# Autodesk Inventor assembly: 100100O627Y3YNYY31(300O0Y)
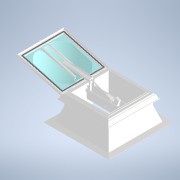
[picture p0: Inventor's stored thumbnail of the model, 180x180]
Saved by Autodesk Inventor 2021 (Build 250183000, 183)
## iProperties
Category: PARTsolutions
Company: KINGSPAN
Created: 2026-04
Part Number: 100100O627Y3YNYY31(300O0Y)
Catalog Web Link: www.3dfindit.com
Description: LK classic-
Vendor: KINGSPAN
Document SubType Name: Assembly
Designer: psAdmin
Manufacturer: KINGSPAN
Mass: 161081 g
Surface Area: 119021 cm^2
Volume: 161081 cm^3
Density: 1 g/cm^3
Title: LKclassic100100O627Y3YNYY31
Author: Cadenas PARTsolutions
PSOL_IDENT_0: {$CADENAS_DATA/23d-libs/kingspan_kla/light_dome_classic/light_dome_classic_asmtab.prj},281 {VTYP=3D}
PSOL_IDENT_1: ,{STYP=ASSTAB},{NB=100100O627Y3YNYY31(300O0Y)},{LINA=LKclassic100100O627Y3YNYY31},{NN=LK classic},{D
PSOL_IDENT_2: ATE=05.11.2025 13:48:10},{GEOMDATE=13.01.2025 13:03:38},{VERSION=},{LINEID=10},{WBVAR=LODLEVEL,L,W,T
PSOL_IDENT_3: G,TS,WF,DP,OP,OC,GCW,SD,IPM,EVADSS,SSSO,SF,BA,INS,RT},{WBNUMERIC=W,RT}  {NB=100100O627Y3YNYY31(300O0
PSOL_IDENT_4: Y)},{LINA=LKclassic100100O627Y3YNYY31},{KT=DUMMY},{IDNR=},{PN=LK classic},{LODLEVEL=300},{L=100},{W=
PSOL_IDENT_5: 100},{DRIVE=1},{WX=100,150,200,250,300},{TG=O},{TS=6},{WF=Y},{DP=2},{OP=7},{OC=O},{SM=N},{GCW=Y},{SD=
PSOL_IDENT_6: 3},{IPM=Y},{EVADSS=N},{SSSO=Y},{SF=Y},{BA=3},{INS=1},{INSX='1','i - insulation','2','ih - enhanced i
PSOL_IDENT_7: nsulation'},{BAX='3', 'AK50 PVC', '2', 'AK30 PVC' , '7'  , 'AK30 AL/ST', '8', 'AK40 AL/ST', '9'  , '
PSOL_IDENT_8: AK50 AL/ST', '13' , 'AK30 AL/AL', '14' , 'AK40 AL/AL', '15' , 'AK50 AL/AL', '16' , 'AK50 ST-TG', '10'
PSOL_IDENT_9: , 'AK30 ST', '11'  , 'AK40 ST', '12', 'AK50 ST'},{UVD=1.9},{UVDU=calculated by excell tool},{LT=13},
PSOL_IDENT_10: {GV=13},{SI=22},{WFX='Y','Yes','N','No'},{OPX='7','Electric Actuator - 24/48 v A/Z'},{TSX='1','2 -sh
PSOL_IDENT_11: elled', '2shell.png','2','3-shelled', '3shell.png','3','PC-st 16/7 + 1 shell','pc16_3.png', '4','PC-
PSOL_IDENT_12: st 16/7 + 2 shells ', 'pcst16_2shells.png', '5','2‐shelled with heat‐stop coating', '2shell.png','6'
PSOL_IDENT_13: ,'3‐shelled with heat‐stop coating', '3shell.png'},{LX=1000},{XWX=1000},{ANG=9.7947},{ROT=-15},{PPAT
PSOL_IDENT_14: H=parts/light_dome_classic_asmtpl.prj},{IBM=LKclassic100100O627Y3YNYY31},{SFX='Y','Yes','N','No'},{D
PSOL_IDENT_15: PX='3', 'Fixed','1', 'Natural ventilation','4','NSHE', '2'  , 'NSHEV'},{OCX='O', 'Open', 'C', 'Close
PSOL_IDENT_16: d'},{SMX='N', 'No'},{VERPRA=ErroR},{EVADSSX='N','No'},{RT=0},{SDX='1', 'RSM - round bar fall-through
PSOL_IDENT_17: protection mat', '2'  , 'EAD - laser cut fall-through protection mat', '3'  , 'HDS - fall through/h
PSOL_IDENT_18: ale protection and shading system'},{OCX1=C},{OPX1='7','Electric Actuator - 24/48 v A/Z'}
NB: 100100O627Y3YNYY31(300O0Y)
NN: LK classic
NBSYN: $L.$W.$TG.$TS.$DP.$OP.$GCW.$SD.$IPM.$EVADSS.$SSSO.$SF.$BA.$INS.($LODLEVEL.$OC.$RT.$WF.)
LINA: LKclassic100100O627Y3YNYY31
CATALOG: Light + Air
PN: LK classic
LODLEVEL: 300
L: 100
W: 100
TG: opal
TS: 3‐shelled with heat‐stop coating opal
DP: NSHEV
OP: NSHEV 24/48 V LK incl. ventilation function
OC: Open
GCW: Yes
SD: HDS - fall through/hale protection and shading system
IPM: Yes
EVADSS: No
SF: Yes
BA: AK PVC 50
INS: i - insulation
UVD: 1.9
LT: 13
GV: 13
SI: 22
RT: 0
SUPPLIER: KINGSPAN
ARTICLENO: 100100O627Y3YNYY31(300O0Y)
BOMINFO: LKclassic100100O627Y3YNYY31
CREATOR: CADENAS GmbH
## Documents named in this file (8)
- e:\temp\worker_COMMON_213\temp\tmp_4108_10_Hp20B\format_0\100100O627Y3YNYY31(300O0Y).iam
- e:\temp\worker_COMMON_213\temp\tmp_4108_10_Hp20B\format_0\Light dome classic(30010010027310)_part_1.ipt
- e:\temp\worker_COMMON_213\temp\tmp_4108_10_Hp20B\format_0\Light dome classic(3001001003Y27O)_part_2.ipt
- e:\temp\worker_COMMON_213\temp\tmp_4108_10_Hp20B\format_0\Light dome classic(30010010027O)_part_3.ipt
- e:\temp\worker_COMMON_213\temp\tmp_4108_10_Hp20B\format_0\Light dome classic(300100100O3)_part_4.ipt
- e:\temp\worker_COMMON_213\temp\tmp_4108_10_Hp20B\format_0\Light dome classic(300100100)_part_6.ipt
- e:\temp\worker_COMMON_213\temp\tmp_4108_10_Hp20B\format_0\Light dome classic(30010010027)_part_11.ipt
- e:\temp\worker_COMMON_213\temp\tmp_4108_10_Hp20B\format_0\Light dome classic(300100100273O)_part_10.ipt
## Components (7 placed, 7 different names)
1. Light dome classic(30010010027310)_part_1:1
2. Light dome classic(3001001003Y27O)_part_2:1
3. Light dome classic(30010010027O)_part_3:1
4. Light dome classic(300100100O3)_part_4:1
5. Light dome classic(300100100)_part_6:1
6. Light dome classic(30010010027)_part_11:1
7. Light dome classic(300100100273O)_part_10:1
